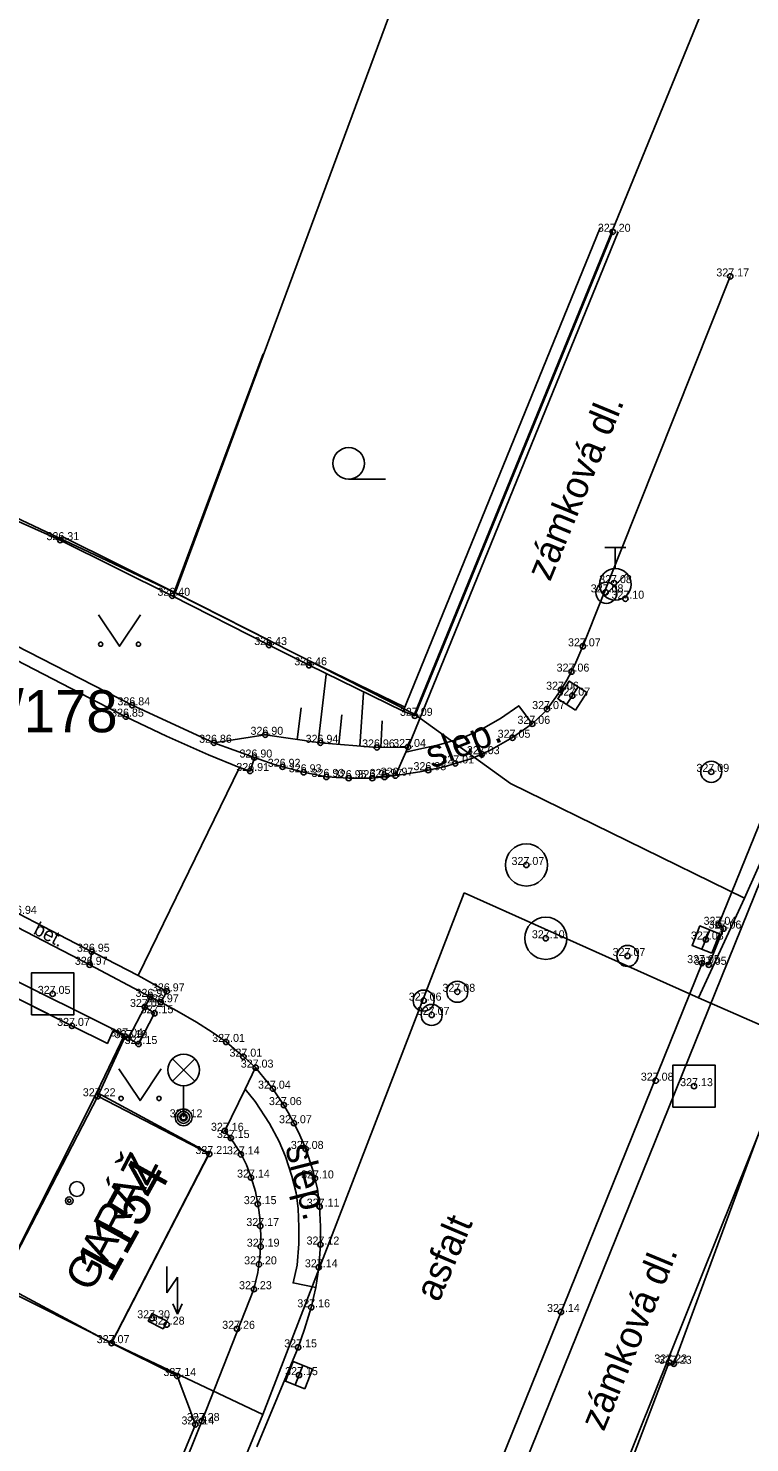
# Model space of a CAD drawing. Extents: x -643859 to -643594, y -1190913 to -1190609.
# Drawn here: x -643701.61 to -643684.48, y -1190794.62 to -1190761.05 of the extents above; entities that cross this region are included whole.
import ezdxf

# ---------------------------------------------------------------- set-up
doc = ezdxf.new("R2010")
doc.units = 0
for name, color, linetype in [('Bodové objekty elektro', 7, 'Continuous'), ('Bodové objekty kanalizace', 7, 'Continuous'), ('Bodové objekty katastrální', 7, 'Continuous'), ('Bodové objekty ostatní', 7, 'Continuous'), ('Bodové objekty plynovody', 7, 'Continuous'), ('Bodové objekty polohopis', 7, 'Continuous'), ('Bodové objekty vodovody', 7, 'Continuous'), ('Bodové objekty značky budov', 7, 'Continuous'), ('Bodové objekty značky předmětů', 7, 'Continuous'), ('Budovy', 7, 'Continuous'), ('Default', 7, 'Continuous'), ('Hranice parcel', 7, 'Continuous'), ('Ploty_podezdívky', 7, 'Continuous'), ('Popis povrchů', 7, 'Continuous'), ('Rozhraní', 7, 'Continuous'), ('Rozhraní_ schody_ zdi', 7, 'Continuous'), ('Svodidla_zábradlí', 7, 'Continuous'), ('Voda', 7, 'Continuous'), ('Vrstva 11', 7, 'Continuous'), ('Vrstva 63', 7, 'Continuous'), ('Vstup do objektu', 7, 'Continuous'), ('Vstup na pozemek', 7, 'Continuous'), ('Šrafy', 7, 'Continuous')]:
    doc.layers.add(name, color=color, linetype=linetype)

msp = doc.modelspace()

# ---------------------------------------------------------------- linework, layer by layer
at = {"layer": 'Bodové objekty elektro'}
for p, q in [((-643698.314, -1190790.443), (-643698.314, -1190791.069)), ((-643698.314, -1190791.069), (-643698.064, -1190790.694)), ((-643698.064, -1190790.694), (-643698.064, -1190791.569)), ((-643698.174, -1190791.324), (-643698.064, -1190791.569)), ((-643698.064, -1190791.569), (-643697.954, -1190791.324))]:
    msp.add_line(p, q, dxfattribs=at)
msp.add_lwpolyline([(-643698.49, -1190791.65), (-643698.668, -1190791.558), (-643698.76, -1190791.736), (-643698.405, -1190791.92), (-643698.313, -1190791.742), (-643698.49, -1190791.65)], dxfattribs=at)
at = {"layer": 'Bodové objekty kanalizace'}
for p, q in [((-643688.826, -1190777.099), (-643688.554, -1190776.681)), ((-643685.613, -1190782.912), (-643685.427, -1190782.448)), ((-643695.272, -1190793.252), (-643695.088, -1190792.788))]:
    msp.add_line(p, q, dxfattribs=at)
for points in [[(-643688.616, -1190777.236), (-643688.344, -1190776.816), (-643688.764, -1190776.544), (-643689.036, -1190776.964)], [(-643685.381, -1190783.005), (-643685.195, -1190782.541), (-643685.659, -1190782.355), (-643685.845, -1190782.819)], [(-643695.04, -1190793.344), (-643694.856, -1190792.88), (-643695.32, -1190792.696), (-643695.504, -1190793.16)]]:
    msp.add_lwpolyline(points, close=True, dxfattribs=at)
for centre in [(-643689.78, -1190780.91), (-643689.32, -1190782.65)]:
    msp.add_circle(centre, 0.5, dxfattribs=at)
at = {"layer": 'Bodové objekty katastrální'}
msp.add_line((-643694.002, -1190771.754), (-643693.127, -1190771.754), dxfattribs=at)
for points in [[(-643699.94, -1190774.97), (-643699.44, -1190775.72), (-643698.94, -1190774.97)], [(-643699.454, -1190785.752), (-643698.954, -1190786.502), (-643698.454, -1190785.752)]]:
    msp.add_lwpolyline(points, dxfattribs=at)
for centre, radius in [((-643694.002, -1190771.379), 0.375), ((-643699.89, -1190775.67), 0.05), ((-643698.991, -1190775.67), 0.05), ((-643699.404, -1190786.452), 0.05), ((-643698.505, -1190786.452), 0.05)]:
    msp.add_circle(centre, radius, dxfattribs=at)
at = {"layer": 'Bodové objekty ostatní'}
for points in [[(-643701.53, -1190784.47), (-643700.53, -1190784.47), (-643700.53, -1190783.47), (-643701.53, -1190783.47)], [(-643686.3, -1190786.66), (-643685.3, -1190786.66), (-643685.3, -1190785.66), (-643686.3, -1190785.66)]]:
    msp.add_lwpolyline(points, close=True, dxfattribs=at)
at = {"layer": 'Bodové objekty plynovody'}
for centre in [(-643685.39, -1190778.7), (-643687.38, -1190783.07)]:
    msp.add_circle(centre, 0.25, dxfattribs=at)
at = {"layer": 'Bodové objekty polohopis'}
for p, q in [((-643698.185, -1190786.04), (-643697.655, -1190785.51)), ((-643698.185, -1190785.51), (-643697.655, -1190786.04)), ((-643697.92, -1190786.15), (-643697.92, -1190786.9))]:
    msp.add_line(p, q, dxfattribs=at)
for centre, radius in [((-643697.92, -1190785.775), 0.375), ((-643697.92, -1190786.9), 0.2), ((-643697.92, -1190786.9), 0.145), ((-643697.92, -1190786.9), 0.0876)]:
    msp.add_circle(centre, radius, dxfattribs=at)
at = {"layer": 'Bodové objekty vodovody'}
for p, q in [((-643687.92, -1190773.375), (-643687.42, -1190773.375)), ((-643687.67, -1190773.875), (-643687.67, -1190773.375)), ((-643687.928, -1190774.522), (-643687.398, -1190773.992))]:
    msp.add_line(p, q, dxfattribs=at)
for centre, radius in [((-643687.67, -1190774.25), 0.375), ((-643687.88, -1190774.45), 0.25), ((-643692.22, -1190784.13), 0.25), ((-643691.42, -1190783.92), 0.25), ((-643692.03, -1190784.47), 0.25)]:
    msp.add_circle(centre, radius, dxfattribs=at)
at = {"layer": 'Bodové objekty značky budov'}
for radius in [0.09, 0.0398]:
    msp.add_circle((-643700.635, -1190788.881), radius, dxfattribs=at)
at = {"layer": 'Budovy'}
for points in [[(-643702.8, -1190783.61), (-643700.57, -1190784.73), (-643699.729, -1190785.147), (-643699.589, -1190784.842), (-643699.31, -1190784.98), (-643699.96, -1190786.4), (-643702.259, -1190790.85)], [(-643702.26, -1190790.85), (-643699.63, -1190792.26), (-643697.309, -1190787.77), (-643699.96, -1190786.4), (-643702.259, -1190790.85)], [(-643690.75, -1190804.15), (-643686.4, -1190792.73), (-643686.288, -1190792.773), (-643684.13, -1190786.91), (-643684.1, -1190786.92), (-643679.438, -1190788.637)]]:
    msp.add_lwpolyline(points, dxfattribs=at)
at = {"layer": 'Default'}
for centre in [(-643687.73, -1190765.88), (-643684.94, -1190766.94), (-643700.85, -1190773.2), (-643687.7, -1190774.22), (-643698.19, -1190774.52), (-643687.9, -1190774.44), (-643687.43, -1190774.59), (-643695.89, -1190775.69), (-643688.44, -1190775.72), (-643694.94, -1190776.17), (-643688.71, -1190776.32), (-643688.96, -1190776.75), (-643688.69, -1190776.89), (-643699.14, -1190777.12), (-643689.29, -1190777.21), (-643699.29, -1190777.39), (-643692.43, -1190777.37), (-643689.64, -1190777.56), (-643695.98, -1190777.82), (-643690.11, -1190777.89), (-643697.2, -1190778.01), (-643694.67, -1190778.01), (-643693.33, -1190778.12), (-643692.59, -1190778.11), (-643690.84, -1190778.28), (-643696.24, -1190778.36), (-643695.57, -1190778.58), (-643691.47, -1190778.5), (-643696.34, -1190778.68), (-643695.07, -1190778.71), (-643694.53, -1190778.82), (-643694, -1190778.85), (-643693.44, -1190778.85), (-643693.15, -1190778.82), (-643692.89, -1190778.79), (-643692.11, -1190778.66), (-643685.39, -1190778.7), (-643689.78, -1190780.91), (-643685.22, -1190782.33), (-643685.1, -1190782.42), (-643700.1, -1190782.97), (-643689.32, -1190782.65), (-643685.52, -1190782.68), (-643700.15, -1190783.28), (-643687.38, -1190783.07), (-643685.61, -1190783.24), (-643685.45, -1190783.28), (-643701.03, -1190783.97), (-643698.32, -1190783.91), (-643691.42, -1190783.92), (-643698.84, -1190784.28), (-643698.71, -1190784.04), (-643698.46, -1190784.17), (-643692.22, -1190784.13), (-643698.61, -1190784.43), (-643692.03, -1190784.47), (-643700.57, -1190784.73), (-643699.31, -1190784.98), (-643699.23, -1190785.02), (-643698.99, -1190785.16), (-643696.91, -1190785.11), (-643696.5, -1190785.46), (-643696.21, -1190785.72), (-643695.8, -1190786.22), (-643686.71, -1190786.03), (-643685.8, -1190786.16), (-643699.96, -1190786.4), (-643695.54, -1190786.61), (-643697.92, -1190786.9), (-643696.94, -1190787.22), (-643695.3, -1190787.04), (-643696.8, -1190787.39), (-643695.02, -1190787.65), (-643697.31, -1190787.77), (-643696.56, -1190787.78), (-643696.32, -1190788.33), (-643694.8, -1190788.35), (-643696.16, -1190788.96), (-643694.69, -1190789.02), (-643696.1, -1190789.48), (-643696.09, -1190789.97), (-643694.67, -1190789.92), (-643696.13, -1190790.39), (-643694.71, -1190790.46), (-643696.25, -1190790.98), (-643698.67, -1190791.67), (-643694.89, -1190791.41), (-643688.96, -1190791.52), (-643698.32, -1190791.82), (-643696.65, -1190791.92), (-643699.63, -1190792.26), (-643695.2, -1190792.36), (-643686.39, -1190792.72), (-643698.07, -1190793.04), (-643695.18, -1190793.02), (-643686.28, -1190792.75), (-643697.64, -1190794.19), (-643697.49, -1190794.11)]:
    msp.add_circle(centre, 0.0625, dxfattribs=at)
at = {"layer": 'Hranice parcel'}
for p, q in [((-643680.72, -1190727.52), (-643698.12, -1190774.45)), ((-643673.19, -1190730.3), (-643692.44, -1190777.33)), ((-643708.25, -1190769.67), (-643698.12, -1190774.45)), ((-643679.3, -1190769.72), (-643684.6, -1190781.7)), ((-643698.12, -1190774.45), (-643692.44, -1190777.33)), ((-643690.16, -1190778.98), (-643692.44, -1190777.33)), ((-643684.6, -1190781.7), (-643690.16, -1190778.98)), ((-643691.26, -1190781.57), (-643696.04, -1190793.95)), ((-643685.69, -1190784.06), (-643691.26, -1190781.57)), ((-643684.6, -1190781.7), (-643685.69, -1190784.06)), ((-643703.09, -1190783.07), (-643699.32, -1190784.94)), ((-643683.43, -1190785.06), (-643685.69, -1190784.06)), ((-643699.32, -1190784.94), (-643699.98, -1190786.31)), ((-643699.98, -1190786.31), (-643702.31, -1190790.91)), ((-643697.31, -1190787.75), (-643699.98, -1190786.31)), ((-643684.1, -1190786.89), (-643693.65, -1190810.62)), ((-643699.63, -1190792.25), (-643697.31, -1190787.75)), ((-643702.31, -1190790.91), (-643699.63, -1190792.25)), ((-643699.63, -1190792.25), (-643696.04, -1190793.95)), ((-643700.89, -1190805.84), (-643696.04, -1190793.95))]:
    msp.add_line(p, q, dxfattribs=at)
at = {"layer": 'Ploty_podezdívky'}
for p, q in [((-643698.145, -1190774.431), (-643696.034, -1190768.781)), ((-643692.67, -1190777.164), (-643694.896, -1190776.08))]:
    msp.add_line(p, q, dxfattribs=at)
for points in [[(-643688.029, -1190765.787), (-643692.708, -1190777.257)], [(-643687.73, -1190765.88), (-643692.43, -1190777.37), (-643692.708, -1190777.257)], [(-643695.845, -1190775.601), (-643695.89, -1190775.69), (-643698.19, -1190774.52), (-643700.85, -1190773.2), (-643700.806, -1190773.11)], [(-643695.845, -1190775.601), (-643698.145, -1190774.431), (-643700.806, -1190773.11)], [(-643692.708, -1190777.257), (-643694.94, -1190776.17), (-643694.896, -1190776.08)], [(-643699.63, -1190792.26), (-643698.07, -1190793.04), (-643697.64, -1190794.19), (-643700.24, -1190800.46)]]:
    msp.add_lwpolyline(points, dxfattribs=at)
at = {"layer": 'Rozhraní'}
for points in [[(-643696.24, -1190778.36), (-643695.769, -1190778.522), (-643695.57, -1190778.58), (-643695.256, -1190778.663), (-643695.07, -1190778.71), (-643694.926, -1190778.74), (-643694.53, -1190778.82), (-643694, -1190778.85), (-643693.44, -1190778.85), (-643693.15, -1190778.82), (-643692.89, -1190778.79), (-643692.307, -1190778.698), (-643692.11, -1190778.66), (-643691.731, -1190778.578), (-643691.47, -1190778.5), (-643691.1, -1190778.39), (-643690.84, -1190778.28), (-643690.611, -1190778.17), (-643690.109, -1190777.888), (-643689.64, -1190777.56), (-643689.361, -1190777.29), (-643689.29, -1190777.21), (-643689.08, -1190776.93), (-643688.96, -1190776.75), (-643688.821, -1190776.526), (-643688.71, -1190776.32), (-643688.631, -1190776.16), (-643688.44, -1190775.72), (-643684.94, -1190766.94)], [(-643696.24, -1190778.36), (-643697.2, -1190778.01), (-643699.14, -1190777.12), (-643702.21, -1190775.54), (-643706.63, -1190773.33), (-643710.42, -1190771.4), (-643713.01, -1190770.06), (-643716.59, -1190768.24)], [(-643693.72, -1190803.31), (-643690.856, -1190796.218), (-643685.61, -1190783.24), (-643685.45, -1190783.28), (-643685.1, -1190782.42), (-643685.22, -1190782.33), (-643682.77, -1190776.31), (-643680.06, -1190769.62)], [(-643698.46, -1190784.17), (-643698.71, -1190784.04), (-643700.15, -1190783.28), (-643702.1, -1190782.27), (-643702.99, -1190781.82), (-643705.6, -1190780.52), (-643707.7, -1190779.45), (-643709.1, -1190778.75), (-643709.56, -1190778.53), (-643713.21, -1190776.72), (-643716.87, -1190774.89), (-643720.25, -1190773.18), (-643724.3, -1190771.18), (-643724.51, -1190771.07), (-643726.23, -1190770.21)], [(-643696.59, -1190778.6), (-643699, -1190783.53)], [(-643698.46, -1190784.17), (-643698.083, -1190784.373), (-643697.611, -1190784.644), (-643697.239, -1190784.878), (-643696.91, -1190785.11), (-643696.654, -1190785.332), (-643696.5, -1190785.46), (-643696.21, -1190785.72), (-643695.8, -1190786.22), (-643695.54, -1190786.61), (-643695.439, -1190786.784), (-643695.301, -1190787.039), (-643695.19, -1190787.25), (-643695.018, -1190787.647), (-643694.851, -1190788.156), (-643694.8, -1190788.35), (-643694.74, -1190788.6), (-643694.689, -1190789.018), (-643694.668, -1190789.495), (-643694.67, -1190789.92), (-643694.708, -1190790.463), (-643694.78, -1190790.94), (-643694.888, -1190791.411), (-643695.046, -1190791.932), (-643695.2, -1190792.36), (-643696.18, -1190794.72)]]:
    msp.add_lwpolyline(points, dxfattribs=at)
at = {"layer": 'Rozhraní_ schody_ zdi'}
msp.add_line((-643698.84, -1190784.28), (-643698.709, -1190784.04), dxfattribs=at)
for points in [[(-643723.8, -1190764.59), (-643723.94, -1190764.9), (-643723.07, -1190765.33), (-643718.8, -1190767.48), (-643716.71, -1190768.53), (-643710.59, -1190771.65), (-643706.74, -1190773.61), (-643702.34, -1190775.82), (-643699.29, -1190777.39), (-643698.322, -1190777.851), (-643697.325, -1190778.298), (-643696.59, -1190778.6), (-643696.34, -1190778.68), (-643696.24, -1190778.36)], [(-643687.605, -1190765.882), (-643692.59, -1190778.11), (-643692.64, -1190778.23), (-643692.89, -1190778.79)], [(-643693.205, -1190803.493), (-643691.553, -1190799.413), (-643682.333, -1190776.603), (-643679.509, -1190769.675)], [(-643692.64, -1190778.23), (-643692.403, -1190778.175), (-643691.861, -1190778.062), (-643691.286, -1190777.891), (-643690.851, -1190777.695), (-643690.392, -1190777.437), (-643689.96, -1190777.13), (-643689.64, -1190777.56)], [(-643702.1, -1190782.27), (-643701.83, -1190782.07), (-643700.1, -1190782.97), (-643700.15, -1190783.28)], [(-643698.46, -1190784.17), (-643698.32, -1190783.91), (-643699, -1190783.53), (-643700.009, -1190783.015), (-643700.1, -1190782.97)], [(-643699.23, -1190785.02), (-643698.99, -1190785.16), (-643698.61, -1190784.43), (-643698.84, -1190784.28), (-643699.23, -1190785.02)], [(-643700.11, -1190800.64), (-643697.49, -1190794.11), (-643696.25, -1190790.98), (-643696.16, -1190790.583), (-643696.13, -1190790.39), (-643696.1, -1190790.136), (-643696.09, -1190789.97), (-643696.086, -1190789.68), (-643696.1, -1190789.48), (-643696.11, -1190789.28), (-643696.141, -1190789.05), (-643696.16, -1190788.96), (-643696.213, -1190788.663), (-643696.317, -1190788.332), (-643696.43, -1190788.03), (-643696.556, -1190787.776), (-643696.742, -1190787.479), (-643696.94, -1190787.22), (-643696.46, -1190786.23), (-643696.21, -1190785.72)], [(-643696.46, -1190786.23), (-643696.222, -1190786.524), (-643695.883, -1190787.046), (-643695.654, -1190787.474), (-643695.5, -1190787.83), (-643695.346, -1190788.299), (-643695.248, -1190788.694), (-643695.203, -1190789.061), (-643695.183, -1190789.505), (-643695.185, -1190789.901), (-643695.221, -1190790.406), (-643695.32, -1190790.83), (-643694.78, -1190790.94)]]:
    msp.add_lwpolyline(points, dxfattribs=at)
at = {"layer": 'Voda'}
msp.add_lwpolyline([(-643697.2, -1190778.01), (-643695.98, -1190777.82), (-643694.67, -1190778.01), (-643693.33, -1190778.12), (-643692.59, -1190778.11)], dxfattribs=at)
at = {"layer": 'Vrstva 11'}
msp.add_circle((-643700.454, -1190788.601), 0.175, dxfattribs=at)
at = {"layer": 'Vstup do objektu'}
msp.add_line((-643700.57, -1190784.73), (-643702.8, -1190783.61), dxfattribs=at)
at = {"layer": 'Vstup na pozemek'}
for p, q in [((-643702.82, -1190772.32), (-643700.85, -1190773.2)), ((-643695.89, -1190775.69), (-643694.94, -1190776.17))]:
    msp.add_line(p, q, dxfattribs=at)
at = {"layer": 'Šrafy'}
for p, q in [((-643694.728, -1190778.002), (-643694.536, -1190776.386)), ((-643693.732, -1190778.087), (-643693.647, -1190776.828)), ((-643695.223, -1190777.93), (-643695.13, -1190777.179)), ((-643694.23, -1190778.046), (-643694.163, -1190777.344)), ((-643693.233, -1190778.119), (-643693.205, -1190777.492))]:
    msp.add_line(p, q, dxfattribs=at)

# ---------------------------------------------------------------- texts
at = {"layer": 'Bodové objekty značky předmětů'}
msp.add_text('GARÁŽ', height=0.75, rotation=62.4182, dxfattribs=at).set_placement((-643700.102, -1190791.077))
at = {"layer": 'Popis povrchů'}
for s, height, rotation, p in [('zámková dl.', 0.64996, 67.5797, (-643689.218, -1190774.201)), ('slep.', 0.65, 21.3638, (-643692.021, -1190778.628)), ('bet.', 0.325, 332.6182, (-643701.508, -1190782.535)), ('slep.', 0.65, 284.3638, (-643695.511, -1190787.61)), ('asfalt', 0.65, 66.9572, (-643691.86, -1190791.312)), ('zámková dl.', 0.64996, 67.5797, (-643687.943, -1190794.375))]:
    msp.add_text(s, height=height, rotation=rotation, dxfattribs=at).set_placement(p)
at = {"layer": 'Svodidla_zábradlí'}
for s, p in [('327.20', (-643688.083, -1190765.88)), ('327.17', (-643685.27, -1190766.94)), ('326.31', (-643701.176, -1190773.2)), ('327.08', (-643688.053, -1190774.22)), ('326.40', (-643698.542, -1190774.52)), ('327.08', (-643688.253, -1190774.44)), ('327.10', (-643687.76, -1190774.59)), ('326.43', (-643696.242, -1190775.69)), ('327.07', (-643688.793, -1190775.72)), ('326.46', (-643695.292, -1190776.17)), ('327.06', (-643689.063, -1190776.32)), ('327.06', (-643689.313, -1190776.75)), ('327.07', (-643689.043, -1190776.89)), ('326.85', (-643699.642, -1190777.39)), ('326.84', (-643699.492, -1190777.12)), ('327.09', (-643692.783, -1190777.37)), ('327.07', (-643689.643, -1190777.21)), ('327.06', (-643689.993, -1190777.56)), ('326.86', (-643697.552, -1190778.01)), ('326.90', (-643696.332, -1190777.82)), ('326.94', (-643695.022, -1190778.01)), ('327.05', (-643690.463, -1190777.89)), ('326.90', (-643696.592, -1190778.36)), ('326.96', (-643693.682, -1190778.12)), ('327.04', (-643692.943, -1190778.11)), ('327.03', (-643691.193, -1190778.28)), ('326.91', (-643696.668, -1190778.68)), ('326.92', (-643695.922, -1190778.58)), ('326.93', (-643695.422, -1190778.71)), ('326.98', (-643692.462, -1190778.66)), ('327.01', (-643691.8, -1190778.5)), ('327.09', (-643685.743, -1190778.7)), ('326.93', (-643694.882, -1190778.82)), ('326.95', (-643694.352, -1190778.85)), ('326.95', (-643693.792, -1190778.85)), ('326.97', (-643693.502, -1190778.82)), ('326.97', (-643693.242, -1190778.79)), ('327.07', (-643690.133, -1190780.91)), ('326.94', (-643702.182, -1190782.07)), ('327.04', (-643685.573, -1190782.33)), ('327.06', (-643685.453, -1190782.42)), ('327.10', (-643689.65, -1190782.65)), ('327.03', (-643685.873, -1190782.68)), ('326.95', (-643700.452, -1190782.97)), ('327.07', (-643687.733, -1190783.07)), ('326.97', (-643700.502, -1190783.28)), ('327.05', (-643685.963, -1190783.24)), ('327.05', (-643685.803, -1190783.28)), ('327.05', (-643701.383, -1190783.97)), ('326.97', (-643699.062, -1190784.04)), ('326.97', (-643698.672, -1190783.91)), ('327.08', (-643691.773, -1190783.92)), ('327.02', (-643699.193, -1190784.28)), ('327.15', (-643698.94, -1190784.43)), ('326.97', (-643698.812, -1190784.17)), ('327.06', (-643692.573, -1190784.13)), ('327.07', (-643700.923, -1190784.73)), ('327.07', (-643692.383, -1190784.47)), ('327.04', (-643699.663, -1190784.98)), ('327.19', (-643699.56, -1190785.02)), ('327.01', (-643697.24, -1190785.11)), ('327.15', (-643699.32, -1190785.16)), ('327.01', (-643696.83, -1190785.46)), ('327.03', (-643696.563, -1190785.72)), ('327.08', (-643687.063, -1190786.03)), ('327.22', (-643700.313, -1190786.4)), ('327.04', (-643696.153, -1190786.22)), ('327.13', (-643686.13, -1190786.16)), ('327.06', (-643695.893, -1190786.61)), ('327.12', (-643698.25, -1190786.9)), ('327.07', (-643695.653, -1190787.04)), ('327.16', (-643697.27, -1190787.22)), ('327.15', (-643697.13, -1190787.39)), ('327.21', (-643697.64, -1190787.77)), ('327.14', (-643696.89, -1190787.78)), ('327.08', (-643695.373, -1190787.65)), ('327.14', (-643696.65, -1190788.33)), ('327.10', (-643695.13, -1190788.35)), ('327.15', (-643696.49, -1190788.96)), ('327.11', (-643694.996, -1190789.02)), ('327.17', (-643696.43, -1190789.48)), ('327.19', (-643696.42, -1190789.97)), ('327.12', (-643695, -1190789.92)), ('327.20', (-643696.483, -1190790.39)), ('327.14', (-643695.04, -1190790.46)), ('327.23', (-643696.603, -1190790.98)), ('327.16', (-643695.22, -1190791.41)), ('327.30', (-643699.021, -1190791.67)), ('327.28', (-643698.673, -1190791.82)), ('327.14', (-643689.29, -1190791.52)), ('327.26', (-643697.003, -1190791.92)), ('327.07', (-643699.983, -1190792.26)), ('327.15', (-643695.53, -1190792.36)), ('327.23', (-643686.743, -1190792.72)), ('327.23', (-643686.633, -1190792.75)), ('327.14', (-643698.4, -1190793.04)), ('327.15', (-643695.51, -1190793.02)), ('327.14', (-643697.97, -1190794.19)), ('327.28', (-643697.843, -1190794.11))]:
    msp.add_text(s, height=0.19, dxfattribs=at).set_placement(p)
at = {"layer": 'Vrstva 63'}
msp.add_text('465/178', height=1, dxfattribs=at).set_placement((-643704.32, -1190777.76))
msp.add_text('1154', height=1, rotation=61.0037, dxfattribs=at).set_placement((-643699.659, -1190790.866))

doc.saveas('drawing.dxf')
